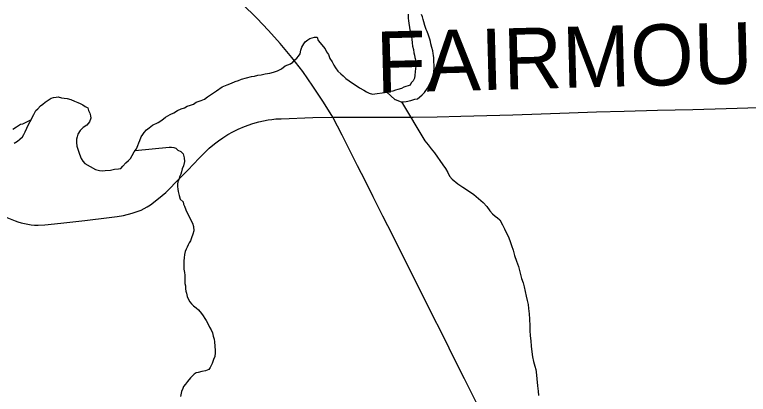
# Model space of a CAD drawing. Extents: x -11.4 to 84.1, y 11.1 to 59.
# Drawn here: x 30.516 to 31.198, y 45.689 to 46.042 of the extents above; entities that cross this region are included whole.
import ezdxf

# ---------------------------------------------------------------- set-up
doc = ezdxf.new("R2010")
doc.units = 0
for name, color, linetype in [('GM_X_County_Road', 7, 'Continuous'), ('GM_X_County_Road_Text', 7, 'Continuous'), ('GM_X_Major_River', 7, 'Continuous'), ('GM_X_Minor_River', 7, 'Continuous'), ('GM_X_Township_Road', 7, 'Continuous')]:
    doc.layers.add(name, color=color, linetype=linetype)

msp = doc.modelspace()

# ---------------------------------------------------------------- linework, layer by layer
at = {"layer": 'GM_X_County_Road'}
for points in [[(30.81127, 45.9465), (30.80276, 45.96043), (30.79284, 45.9753), (30.78345, 45.98887), (30.77331, 46.00193), (30.76253, 46.01486), (30.75162, 46.02704), (30.74071, 46.03846), (30.7272, 46.05177), (30.71369, 46.06508), (30.69357, 46.08492), (30.67345, 46.10475)], [(30.81127, 45.9465), (30.83766, 45.94662), (30.86195, 45.9465), (30.88624, 45.94637), (30.90838, 45.94687), (30.93051, 45.94736), (30.95467, 45.94809), (30.97884, 45.94883), (31.00498, 45.94976), (31.03112, 45.95069), (31.05671, 45.95137), (31.0823, 45.95204), (31.11335, 45.95288), (31.1297, 45.95333), (31.14604, 45.95377), (31.1771, 45.95467), (31.2074, 45.95554)], [(30.67647, 45.89738), (30.68702, 45.90838), (30.69267, 45.91392), (30.69654, 45.91772), (30.70135, 45.92179), (30.70523, 45.92447), (30.70921, 45.92734), (30.71392, 45.93048), (30.7183, 45.93301), (30.72328, 45.93535), (30.72928, 45.93788), (30.73695, 45.94065), (30.74269, 45.9422), (30.74685, 45.94315), (30.75119, 45.94398), (30.75474, 45.94448), (30.75853, 45.94482), (30.7635, 45.94507), (30.7929, 45.94611), (30.81127, 45.9465)], [(30.94776, 45.67535), (30.93389, 45.70315), (30.92436, 45.72224), (30.91484, 45.74132), (30.90171, 45.76752), (30.88858, 45.79373), (30.87785, 45.81511), (30.86712, 45.83651), (30.85801, 45.85448), (30.8489, 45.87245), (30.84166, 45.88691), (30.83443, 45.90136), (30.82729, 45.91564), (30.82015, 45.92991), (30.81127, 45.9465)], [(30.49875, 45.85689), (30.51623, 45.85014), (30.51865, 45.84925), (30.52168, 45.84832), (30.52476, 45.84754), (30.52784, 45.84693), (30.53101, 45.84647), (30.53414, 45.84619), (30.53731, 45.84607), (30.54366, 45.84632), (30.55854, 45.84791), (30.58099, 45.85055), (30.60345, 45.85318), (30.61086, 45.85405), (30.6167, 45.85522), (30.62489, 45.85727), (30.63316, 45.86019), (30.63872, 45.86321), (30.64193, 45.86516), (30.64934, 45.87081), (30.65616, 45.87656), (30.66917, 45.88979), (30.67647, 45.89738)]]:
    msp.add_lwpolyline(points, dxfattribs=at)
at = {"layer": 'GM_X_Major_River'}
for points in [[(30.88133, 46.0421), (30.88139, 46.03868), (30.88181, 46.03602), (30.88223, 46.03375), (30.88267, 46.02995), (30.88309, 46.02768), (30.88389, 46.02541), (30.88431, 46.02276), (30.88476, 46.01896), (30.88519, 46.01555), (30.88563, 46.01251), (30.88643, 46.00948), (30.88686, 46.00645), (30.88729, 46.00417), (30.8877, 46.0019), (30.88851, 45.99887), (30.88894, 45.99621), (30.8886, 45.99355), (30.88825, 45.99164), (30.8876, 45.98555), (30.88726, 45.98288), (30.88617, 45.9802), (30.8843, 45.97827), (30.88319, 45.97635), (30.88131, 45.97556), (30.87942, 45.97514), (30.87753, 45.97435), (30.87527, 45.97317), (30.87186, 45.97236), (30.8696, 45.97156), (30.86733, 45.97076), (30.86317, 45.96993), (30.86174, 45.9697)], [(30.89546, 46.03739), (30.89467, 46.03966), (30.89387, 46.04193)], [(30.86174, 45.9697), (30.86899, 45.96281), (30.86936, 45.96281), (30.8751, 45.96062), (30.877, 45.96065), (30.87965, 45.96108), (30.88382, 45.96191), (30.88759, 45.96311), (30.89024, 45.96353), (30.89212, 45.96509), (30.89436, 45.9674), (30.8966, 45.96934), (30.89957, 45.97357), (30.90104, 45.97664), (30.90251, 45.97933), (30.90361, 45.98201), (30.90433, 45.98468), (30.90541, 45.98812), (30.9057, 45.99307), (30.90567, 45.99497), (30.90524, 45.998), (30.90518, 46.00181), (30.90515, 46.00371), (30.90473, 46.0056), (30.90431, 46.00826), (30.9035, 46.01128), (30.90268, 46.01469), (30.90226, 46.01697), (30.90147, 46.01886), (30.90106, 46.02075), (30.90027, 46.02264), (30.89907, 46.02604), (30.89828, 46.02793), (30.89749, 46.02982), (30.89708, 46.03171), (30.89588, 46.03512), (30.89546, 46.03739)], [(30.68181, 45.95859), (30.68443, 45.96054), (30.68896, 45.96213), (30.69198, 45.96332), (30.69499, 45.96527), (30.69874, 45.968), (30.70325, 45.97111), (30.7085, 45.97462), (30.71303, 45.9766), (30.71718, 45.97818), (30.72057, 45.97976), (30.7236, 45.98057), (30.72661, 45.98176), (30.73569, 45.98419), (30.73872, 45.98462), (30.74175, 45.98543), (30.74478, 45.98586), (30.74856, 45.98669), (30.75273, 45.98752), (30.75613, 45.98833), (30.75991, 45.98953), (30.76368, 45.9915), (30.76705, 45.99421), (30.77195, 45.9962), (30.77421, 45.99775), (30.77607, 45.99969), (30.77795, 46.00124), (30.77943, 46.00316), (30.78091, 46.00547), (30.78161, 46.0089), (30.78271, 46.01158), (30.78456, 46.01466), (30.78566, 46.01658), (30.78829, 46.01852), (30.79017, 46.01969), (30.79433, 46.0209), (30.79699, 46.02094), (30.7978, 46.01792), (30.80439, 46.01004), (30.80557, 46.00739), (30.80751, 46.00477), (30.80872, 46.00098), (30.81067, 45.99797), (30.81223, 45.99495), (30.8138, 45.99232), (30.81613, 45.98931), (30.81883, 45.9867), (30.82114, 45.98483), (30.82346, 45.98259), (30.82653, 45.98036), (30.82961, 45.97813), (30.83306, 45.9759), (30.83614, 45.97367), (30.84036, 45.97146), (30.84266, 45.96998), (30.84534, 45.96888), (30.84839, 45.96779), (30.86174, 45.9697)], [(30.531, 45.94418), (30.53162, 45.94548), (30.53346, 45.94893), (30.5353, 45.95276), (30.53717, 45.95432), (30.53978, 45.95702), (30.54166, 45.95857), (30.5439, 45.96051), (30.54691, 45.96246), (30.54954, 45.96403), (30.55181, 45.96482), (30.55408, 45.96524), (30.55598, 45.96527), (30.55903, 45.96456), (30.56169, 45.96423), (30.56436, 45.96389), (30.56779, 45.96281), (30.57123, 45.96134), (30.57429, 45.96025), (30.57659, 45.95915), (30.57889, 45.95804), (30.58119, 45.95656), (30.5835, 45.95508), (30.58429, 45.95281), (30.58548, 45.95017), (30.58627, 45.9479), (30.58631, 45.94562), (30.58523, 45.94218), (30.58262, 45.93909), (30.57924, 45.93675), (30.57663, 45.93405), (30.57441, 45.93059), (30.57369, 45.9283), (30.57297, 45.926), (30.57302, 45.92296), (30.57345, 45.91955), (30.57466, 45.91577), (30.57586, 45.91198), (30.57744, 45.9082), (30.57901, 45.90557), (30.58094, 45.90332), (30.59091, 45.89778), (30.59434, 45.89707), (30.59701, 45.89674), (30.59966, 45.89678), (30.60459, 45.89724), (30.60838, 45.89807), (30.61217, 45.89851), (30.61444, 45.89893), (30.61631, 45.90086), (30.61891, 45.90394), (30.62154, 45.90627), (30.6234, 45.9082), (30.62487, 45.91088), (30.62672, 45.91434), (30.62895, 45.91704), (30.63004, 45.92009), (30.63113, 45.92278), (30.63186, 45.92469), (30.63332, 45.92813), (30.6348, 45.93044), (30.63591, 45.93236), (30.63815, 45.93468), (30.64078, 45.93662), (30.64377, 45.93895), (30.64904, 45.9417), (30.65243, 45.94366), (30.6558, 45.94638), (30.66032, 45.94911), (30.66371, 45.95069), (30.66709, 45.95265), (30.67048, 45.95422), (30.67351, 45.95503), (30.67614, 45.9566), (30.67916, 45.95779), (30.68181, 45.95859)], [(30.531, 45.94418), (30.52298, 45.94001), (30.52108, 45.9396), (30.5192, 45.93843), (30.51733, 45.93726), (30.51395, 45.93492)], [(30.5153, 45.9224), (30.5183, 45.92435), (30.52056, 45.92591), (30.52279, 45.92822), (30.52428, 45.93053), (30.52538, 45.93283), (30.52684, 45.93627), (30.52831, 45.93896), (30.53015, 45.94241), (30.531, 45.94418)]]:
    msp.add_lwpolyline(points, dxfattribs=at)
at = {"layer": 'GM_X_Minor_River'}
for points in [[(30.87541, 45.96063), (30.89697, 45.92448), (30.90008, 45.92073), (30.9028, 45.91697), (30.9059, 45.91322), (30.91368, 45.90231), (30.91602, 45.89893), (30.91836, 45.89517), (30.91993, 45.89177), (30.92226, 45.88877), (30.92765, 45.88467), (30.93226, 45.88133), (30.93764, 45.87799), (30.94263, 45.87465), (30.94687, 45.87092), (30.95111, 45.86718), (30.95459, 45.86344), (30.95732, 45.8593), (30.96002, 45.85668), (30.96234, 45.85444), (30.96465, 45.85296), (30.96658, 45.85109), (30.96931, 45.84657), (30.97089, 45.84279), (30.97247, 45.8394), (30.97442, 45.836), (30.97601, 45.83185), (30.97761, 45.82731), (30.9792, 45.82277), (30.98043, 45.81785), (30.98203, 45.81255), (30.98401, 45.80764), (30.98564, 45.80158), (30.98686, 45.79666), (30.98845, 45.7925), (30.98927, 45.78872), (30.9901, 45.78455), (30.99131, 45.78), (30.99214, 45.77621), (30.99296, 45.77242), (30.9934, 45.76863), (30.99387, 45.76369), (30.99433, 45.75876), (30.99443, 45.75268), (30.99451, 45.74811), (30.99497, 45.74318), (30.99543, 45.73862), (30.99589, 45.73369), (30.99636, 45.72837), (30.99719, 45.72382), (30.99803, 45.71927), (30.99924, 45.71511), (31.00005, 45.71208), (31.00047, 45.7098), (31.00182, 45.6969), (31.00229, 45.69196), (31.00274, 45.68779)], [(30.6276, 45.9154), (30.65931, 45.91867), (30.66158, 45.91871), (30.66349, 45.91836), (30.6654, 45.91763), (30.66733, 45.91576), (30.67001, 45.91467), (30.67233, 45.91242), (30.67315, 45.90863), (30.67359, 45.90522), (30.67251, 45.9014), (30.67142, 45.89834), (30.67071, 45.89567), (30.66999, 45.89337), (30.66889, 45.89107), (30.66817, 45.8884), (30.66744, 45.88649), (30.6671, 45.8842), (30.66714, 45.88192), (30.66718, 45.87964), (30.6676, 45.87736), (30.66842, 45.87357), (30.66961, 45.87017), (30.67231, 45.86793), (30.67273, 45.86566), (30.67352, 45.86377), (30.67472, 45.86037), (30.6759, 45.85773), (30.67825, 45.85358), (30.67983, 45.85018), (30.681, 45.84792), (30.68181, 45.84489), (30.68226, 45.84072), (30.68118, 45.83766), (30.68009, 45.83422), (30.679, 45.83154), (30.67789, 45.82962), (30.67679, 45.8277), (30.67606, 45.82578), (30.67495, 45.82387), (30.67423, 45.82157), (30.67351, 45.8189), (30.67319, 45.81585), (30.67286, 45.81281), (30.67293, 45.80862), (30.67298, 45.8052), (30.67341, 45.80217), (30.67384, 45.79951), (30.67389, 45.79647), (30.67393, 45.79381), (30.67397, 45.79191), (30.67438, 45.78963), (30.67443, 45.78697), (30.67485, 45.7847), (30.67526, 45.7828), (30.67607, 45.77977), (30.67725, 45.77713), (30.67843, 45.77487), (30.67998, 45.77299), (30.68191, 45.77112), (30.68422, 45.76926), (30.68653, 45.7674), (30.68925, 45.76402), (30.6908, 45.76176), (30.69236, 45.75951), (30.69353, 45.75763), (30.69549, 45.75424), (30.69668, 45.75121), (30.69823, 45.74896), (30.69943, 45.74593), (30.70024, 45.7429), (30.70104, 45.74026), (30.70146, 45.7376), (30.70198, 45.72962), (30.70202, 45.72734), (30.70169, 45.72392), (30.7006, 45.72124), (30.69914, 45.71741), (30.6973, 45.71396), (30.69619, 45.71204), (30.69318, 45.71085), (30.68977, 45.71003), (30.68637, 45.70921), (30.68447, 45.7088), (30.6826, 45.70763), (30.67924, 45.70415), (30.67625, 45.70068), (30.6744, 45.69837), (30.67253, 45.69606), (30.67181, 45.69415), (30.67071, 45.69147), (30.66965, 45.68688)]]:
    msp.add_lwpolyline(points, dxfattribs=at)
at = {"layer": 'GM_X_Township_Road'}
for points in [[(30.81127, 45.9465), (30.80276, 45.96043), (30.79284, 45.9753), (30.78345, 45.98887), (30.77331, 46.00193), (30.76253, 46.01486), (30.75162, 46.02704), (30.74071, 46.03846), (30.7272, 46.05177), (30.71369, 46.06508), (30.69357, 46.08492), (30.67345, 46.10475)], [(30.94776, 45.67535), (30.93389, 45.70315), (30.92436, 45.72224), (30.91484, 45.74132), (30.90171, 45.76752), (30.88858, 45.79373), (30.87785, 45.81511), (30.86712, 45.83651), (30.85801, 45.85448), (30.8489, 45.87245), (30.84166, 45.88691), (30.83443, 45.90136), (30.82729, 45.91564), (30.82015, 45.92991), (30.81127, 45.9465)]]:
    msp.add_lwpolyline(points, dxfattribs=at)

# ---------------------------------------------------------------- texts
at = {"layer": 'GM_X_County_Road_Text'}
msp.add_text('FAIRMOUNT', height=0.056818, rotation=1.48947, dxfattribs=at).set_placement((30.85228, 45.9691))

doc.saveas('drawing.dxf')
